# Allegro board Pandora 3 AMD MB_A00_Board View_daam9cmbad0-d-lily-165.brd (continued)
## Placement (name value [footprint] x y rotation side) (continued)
PC9094  *330P/50V_4_NC  [C0402]  116.36 149.12 90 top
PC9095  1000P/50V_4  [C0402]  116.03 150.51 0 bottom
PC9096  10U/25V_8  [C0805]  97.9 142.99 90 bottom
PC9097  10U/25V_8  [C0805]  102.05 146.49 180 bottom
PC9098  0.22U/25V_6  [C0603]  110.43 150.01 90 bottom
PC9099  680P/50V_4  [C0402]  113.92 150.51 180 bottom
PC9100  0.1U/16V_4  [C0402]  116.33 149.12 90 bottom
PC9101  22n/25V_4  [C0402]  117.29 149.12 270 bottom
PC9102  390P/50V_4  [C0402]  113.31 149.12 270 top
PC9103  2200P/50V_4  [C0402]  97.71 136.26 270 bottom
PC9104  150P/50V_4  [C0402]  114.33 149.12 270 top
PC9105  1U/6.3V_4  [C0402]  107.74 143.3 0 bottom
PC9106  1U/6.3V_4  [C0402]  107.74 144.26 0 bottom
PC9107  0.1U/16V_4  [C0402]  107.15 129.7 180 bottom
PC9108  22U/6.3V_6  [C0603]  99.78 129.9 0 top
PC9109  22U/6.3V_6  [C0603]  99.78 131.31 0 top
PC9110  330U/2V/E6_7343  [CC7343]  106.49 126.85 0 bottom
PC9111  0.1U/16V_4  [C0402]  119.32 149.12 90 bottom
PC9112  10U/25V_8  [C0805]  76.65 144.92 0 bottom
PC9113  10U/25V_8  [C0805]  76.65 144.92 0 top
PC9114  0.22U/25V_6  [C0603]  107.13 146.38 180 bottom
PC9115  2200P/50V_4  [C0402]  78.8 135.37 90 top
PC9116  0.1U/16V_4  [C0402]  89.34 132.49 180 bottom
PC9117  22U/6.3V_6  [C0603]  73.68 127.02 90 bottom
PC9119  22U/6.3V_6  [C0603]  72.26 127.02 90 bottom
PC9120  330U/2V/E6_7343  [CC7343]  75.96 132.91 90 top
PC9121  330U/2V/E6_7343  [CC7343]  73.98 103.81 270 top
PC9122  1000P/50V_4  [C0402]  115.64 145.2 180 top
PC9123  1000P/50V_4  [C0402]  115.65 142.2 180 top
PC9124  0.22U/25V_6  [C0603]  118.58 141.24 0 bottom
PC9125  120P/50V_4  [C0402]  110.82 138.07 90 bottom
PC9126  0.22U/25V_6  [C0603]  118.58 139.83 180 bottom
PC9127  390P/50V_4  [C0402]  109.8 138.07 90 bottom
PC9128  10U/25V_8  [C0805]  90.11 140.7 180 bottom
PC9129  10U/25V_8  [C0805]  88.5 142.67 90 top
PC9130  15U/25V/E100_3528  [C3528]  80.28 140.83 90 bottom
PC9131  680P/50V_4  [C0402]  111.61 136.25 270 bottom
PC9132  0.22U/25V_6  [C0603]  106.73 141.9 180 bottom
PC9133  1000P/50V_4  [C0402]  112.85 138.07 90 bottom
PC9134  0.15U/10V_4  [C0402]  115.9 138.07 90 bottom
PC9135  33n/16V_4  [C0402]  116.91 138.07 270 bottom
PC9136  *330P/50V_4_NC  [C0402]  114.76 135.5 0 bottom
PC9137  2200P/50V_4  [C0402]  87.95 137.77 270 bottom
PC9138  22U/6.3V_6  [C0603]  75.09 127.02 90 bottom
PC9140  330U/2V/E6_7343  [CC7343]  85.79 132.95 90 top
PC9141  0.1U/16V_4  [C0402]  120.39 140.47 270 bottom
PC9142  0.1U/16V_4  [C0402]  86.9 127.44 180 top
PC9143  22U/6.3V_6  [C0603]  70.85 127.02 90 bottom
PC9144  0.01U/50V_4  [C0402]  113.02 135.5 180 bottom
PC9145  1U/6.3V_4  [C0402]  39.43 126.7 270 bottom
PC9146  1U/6.3V_4  [C0402]  40.83 126.85 0 bottom
PC9147  10U/25V_8  [C0805]  72.09 142.69 90 bottom
PC9148  10U/25V_8  [C0805]  72.09 142.69 90 top
PC9149  0.22U/25V_6  [C0603]  42.84 127.28 90 bottom
PC9150  2200P/50V_4  [C0402]  71.41 137.13 180 top
PC9151  0.1U/16V_4  [C0402]  56.67 99.88 90 top
PC9152  22U/6.3V_6  [C0603]  60.74 116.73 0 top
PC9153  22U/6.3V_6  [C0603]  67.47 116.73 0 top
PC9154  22U/6.3V_6  [C0603]  57.95 115.31 180 top
PC9155  330U/2V/E6_7343  [CC7343]  59.97 132.93 90 top
PC9156  1000P/50V_4  [C0402]  35.46 116.99 270 top
PC9157  0.22U/25V_6  [C0603]  33.85 114.89 180 bottom
PC9158  10U/25V_8  [C0805]  54.37 140.7 0 bottom
PC9159  10U/25V_8  [C0805]  54.37 140.7 0 top
PC9160  15U/25V/E100_3528  [C3528]  63.83 140.45 90 bottom
PC9161  0.22U/25V_6  [C0603]  38.21 127.21 90 bottom
PC9162  120P/50V_4  [C0402]  33 127.16 90 bottom
PC9163  0.22U/25V_6  [C0603]  33.85 113.39 0 bottom
PC9164  390P/50V_4  [C0402]  32.92 128.5 0 bottom
PC9165  2200P/50V_4  [C0402]  56.96 136.5 90 top
PC9166  680P/50V_4  [C0402]  30.88 122.84 180 bottom
PC9167  22U/6.3V_6  [C0603]  57.95 116.73 180 top
PC9168  22U/6.3V_6  [C0603]  64.24 116.73 180 top
PC9169  330U/2V/E6_7343  [CC7343]  66.23 103.81 270 top
PC9170  1000P/50V_4  [C0402]  34.39 123.85 0 bottom
PC9171  0.1U/16V_4  [C0402]  58.79 100.31 90 top
PC9172  22U/6.3V_6  [C0603]  57.95 118.14 180 top
PC9173  330U/2V/E6_7343  [CC7343]  67.85 132.93 90 top
PC9174  0.15U/10V_4  [C0402]  34.52 119.3 0 bottom
PC9175  33n/16V_4  [C0402]  34.06 117.67 90 bottom
PC9176  *330P/50V_4_NC  [C0402]  30.8 117.33 180 bottom
PC9177  0.1U/16V_4  [C0402]  31.94 114.66 90 bottom
PC9178  0.01U/50V_4  [C0402]  34.09 121.51 270 bottom
PC9186  0.01U/50V_4  [C0402]  34.71 110.83 270 bottom
PC9190  10U/25V_8  [C0805]  142.81 31.72 0 top
PC9191  10U/25V_8  [C0805]  142.81 31.72 0 bottom
PC9192  0.1U/25V_4  [C0402]  142.89 30.25 0 bottom
PC9193  0.1U/25V_6  [C0603]  140.78 39.48 90 bottom
PC9194  2200P/50V_4  [C0402]  136.34 36.3 0 top
PC9195  22U/6.3V_8  [C0805]  125.41 39.48 270 bottom
PC9196  22U/6.3V_8  [C0805]  129.73 39.48 270 bottom
PC9197  22U/6.3V_8  [C0805]  129.73 39.48 270 top
PC9198  22U/6.3V_8  [C0805]  127.57 39.48 270 bottom
PC9199  22U/6.3V_8  [C0805]  127.57 39.48 270 top
PC9200  0.1U/16V_4  [C0402]  125.92 39.35 270 top
PC9201  0.01U/50V_4  [C0402]  147.62 37.66 180 bottom
PC9202  4.7U/10V_6  [C0603]  143.83 39.48 270 bottom
PC9203  10U/6.3V_4  [C0402]  123.3 50.09 90 bottom
PC9204  0.1U/25V_4  [C0402]  123.28 52.76 90 bottom
PC9205  10U/6.3V_4  [C0402]  118.38 51.69 0 bottom
PC9206  10U/6.3V_4  [C0402]  118.38 52.76 0 bottom
PC9207  0.1U/25V_4  [C0402]  124.65 54.44 180 bottom
PC9208  0.01U/50V_4  [C0402]  126.2 48.14 90 bottom
PC9209  0.033U/50V_6  [C0603]  122.03 48.09 90 bottom
PC9210  10U/6.3V_6  [C0603]  118.34 29.57 90 bottom
PC9211  0.1U/16V_4  [C0402]  117.16 29.78 90 bottom
PC9212  0.01U/50V_4  [C0402]  120.08 30.08 90 bottom
PC9213  1U/6.3V_4  [C0402]  117.41 32.35 270 bottom
PC9214  10U/6.3V_6  [C0603]  117.79 42.62 270 bottom
PC9216  10U/25V_8  [C0805]  16.29 36.73 0 bottom
PC9217  10U/25V_8  [C0805]  19.36 34.3 90 top
PC9219  *2200P/50V_4_NC  [C0402]  22.21 35.44 0 top
PC9221  0.1U/16V_4  [C0402]  17.46 27.21 90 bottom
PC9222  10U/4V_8  [C0805]  15.66 43.64 0 bottom
PC9225  22U/6.3V_8  [C0805]  27.17 27.13 90 bottom
PC9226  22U/6.3V_8  [C0805]  25.13 27.13 90 bottom
PC9227  22U/6.3V_8  [C0805]  25.13 27.13 90 top
PC9228  22U/6.3V_8  [C0805]  27.17 27.13 90 top
PC9229  22U/6.3V_8  [C0805]  15.91 27.54 90 bottom
PC9230  10U/4V_8  [C0805]  15.66 41.61 0 bottom
PC9233  10U/6.3V_6  [C0603]  15.98 53.6 0 bottom
PC9234  0.1U/16V_4  [C0402]  16.41 54.84 0 bottom
PC9235  1U/6.3V_4  [C0402]  16.41 52.35 0 bottom
PC9236  1U/6.3V_4  [C0402]  19.91 56.43 180 bottom
PC9237  10U/6.3V_6  [C0603]  26.7 55.09 270 bottom
PC9238  10U/25V_8  [C0805]  158.06 61.96 0 bottom
PC9239  10U/25V_8  [C0805]  158.06 61.96 0 top
PC9240  *330P/50V_4_NC  [C0402]  146.54 47.7 0 top
PC9241  0.22U/25V_6  [C0603]  147.41 55.1 90 bottom
PC9242  1000P/50V_4  [C0402]  147.14 48.06 270 bottom
PC9243  2200P/50V_4  [C0402]  154.12 65.26 90 top
PC9244  680P/50V_4  [C0402]  149.22 49.92 90 bottom
PC9245  0.01U/50V_4  [C0402]  148.33 44.75 180 bottom
PC9246  47n/16V_4  [C0402]  146.49 44.75 0 bottom
PC9247  0.1U/16V_4  [C0402]  156.02 76.43 270 top
PC9248  22U/6.3V_6  [C0603]  147.54 80.63 270 bottom
PC9249  22U/6.3V_6  [C0603]  150.46 80.63 270 top
PC9250  330U/2V/E6_7343  [CC7343]  150.69 74.4 270 top
PC9251  390P/50V_4  [C0402]  146.54 49.8 180 top
PC9252  100P/50V_4  [C0402]  146.08 49.92 90 bottom
PC9253  1U/6.3V_4  [C0402]  139.31 55.05 180 bottom
PC9254  1U/6.3V_4  [C0402]  141.06 55.05 0 bottom
PC9255  0.1U/16V_4  [C0402]  147.14 46.21 270 bottom
PC9256  10U/25V_8  [C0805]  131.13 59.8 270 top
PC9258  10U/25V_8  [C0805]  133.29 59.8 270 top
PC9259  0.22U/25V_6  [C0603]  143.15 55.1 90 bottom
PC9260  2200P/50V_4  [C0402]  141.67 66.78 0 top
PC9261  0.1U/16V_4  [C0402]  137.2 96.92 90 top
PC9262  330U/2V/E6_7343  [CC7343]  137.22 74.4 270 top
PC9263  330U/2V/E6_7343  [CC7343]  129.6 74.4 270 top
PC9264  *0.1U/16V_4_NC  [C0402]  138.34 42.88 270 bottom
PC9265  1000P/50V_4  [C0402]  141.17 47.44 90 top
PC9266  1000P/50V_4  [C0402]  140.15 47.44 90 top
PC9267  15U/25V/E100_3528  [C3528]  138.49 61.57 270 bottom
PC9268  0.22U/25V_6  [C0603]  135.98 44.53 270 bottom
PC9269  10U/25V_8  [C0805]  147.77 59.8 270 top
PC9270  10U/25V_8  [C0805]  145.73 59.8 270 top
PC9271  100P/50V_4  [C0402]  135.39 50.76 0 top
PC9272  0.22U/25V_6  [C0603]  137.75 55.22 90 bottom
PC9273  0.22U/25V_6  [C0603]  134.56 44.53 90 bottom
PC9274  390P/50V_4  [C0402]  135.4 51.77 0 bottom
PC9275  680P/50V_4  [C0402]  135.39 52.79 180 top
PC9276  2200P/50V_4  [C0402]  129.73 66.53 180 top
PC9277  330U/2V/E6_7343  [CC7343]  145.86 74.4 270 top
PC9278  1000P/50V_4  [C0402]  133.36 49.74 0 bottom
PC9279  0.1U/16V_4  [C0402]  125.87 77.42 90 top
PC9280  330U/2V/E6_7343  [CC7343]  139.26 106.53 0 top
PC9281  0.22U/16V_4  [C0402]  135.6 46.41 0 bottom
PC9282  68n/16V_4  [C0402]  135.6 47.38 0 bottom
PC9283  *330P/50V_4_NC  [C0402]  135.4 48.72 0 bottom
PC9284  0.1U/16V_4  [C0402]  135.8 42.6 180 bottom
PC9285  0.01U/50V_4  [C0402]  136 49.33 270 top
PC9286  10U/25V_8  [C0805]  165.67 63.86 270 bottom
PC9287  10U/25V_8  [C0805]  165.8 63.86 270 top
PC9288  0.1U/25V_4  [C0402]  167.16 59.42 90 bottom
PC9289  0.1U/25V_6  [C0603]  174.33 66.3 0 bottom
PC9290  2200P/50V_4  [C0402]  165.43 67.92 0 bottom
PC9291  22U/6.3V_8  [C0805]  165.9 78.97 0 bottom
PC9292  22U/6.3V_8  [C0805]  165.9 76.97 0 bottom
PC9293  22U/6.3V_8  [C0805]  173.67 77.2 180 bottom
PC9294  22U/6.3V_8  [C0805]  173.8 79.35 180 bottom
PC9295  0.1U/16V_4  [C0402]  174.69 73.64 180 bottom
PC9296  *0.1U/25V_4_NC  [C0402]  171.08 59.42 90 bottom
PC9297  0.01U/50V_4  [C0402]  173.06 59.42 90 bottom
PC9298  4.7U/10V_6  [C0603]  174.33 63.43 180 bottom
PC9299  *0.1u/16V_4_NC  [C0402]  123.09 63.09 180 bottom
PC9300  *0.1u/16V_4_NC  [C0402]  116.19 69.19 180 bottom
PC9301  *0.1u/16V_4_NC  [C0402]  113.45 63.09 180 bottom
PC9302  22u/6.3V_6  [C0603]  113.5 69.5 0 bottom
PC9303  22u/6.3V_6  [C0603]  121.77 69.11 180 bottom
PC9304  0.1u/16V_4  [C0402]  121.49 67.82 180 bottom
PC9305  0.1U/10V_4  [C0402]  124.88 27.11 180 bottom
PC9306  0.1U/10V_4  [C0402]  165.42 26.14 0 bottom
PC9307  0.1U/10V_4  [C0402]  165.37 21.29 0 bottom
PC9308  0.1U/10V_4  [C0402]  124.88 22.41 180 bottom
PC9309  10U/6.3V_4  [C0402]  118.28 27.49 0 bottom
PC9310  0.1U/10V_4  [C0402]  118.28 26.34 0 bottom
PC9311  0.1U/10V_4  [C0402]  118.28 23.17 0 bottom
PC9312  10U/6.3V_4  [C0402]  120.82 22.33 180 bottom
PC9313  10U/6.3V_4  [C0402]  161.71 26.5 0 bottom
PC9314  0.1U/10V_4  [C0402]  161.71 25.48 0 bottom
PC9315  0.1U/10V_4  [C0402]  160.82 22.31 0 bottom
PC9316  10U/6.3V_4  [C0402]  160.85 21.29 0 bottom
PC9317  0.1U/10V_4  [C0402]  124.88 24.82 0 bottom
PC9318  0.1U/10V_4  [C0402]  168.31 24.34 0 bottom
PC9319  0.01U/50V_4  [C0402]  124.88 25.96 180 bottom
PC9320  0.1U/10V_4  [C0402]  124.88 23.68 180 bottom
PC9321  0.01U/50V_4  [C0402]  168.31 25.38 180 bottom
PC9322  0.1U/10V_4  [C0402]  168.31 22.98 180 bottom
PC9323  1000P/50V_4  [C0402]  118.28 25.2 0 bottom
PC9324  1000P/50V_4  [C0402]  118.28 24.19 0 bottom
PC9325  1000P/50V_4  [C0402]  161.71 24.34 0 bottom
PC9326  1000P/50V_4  [C0402]  161.71 23.32 0 bottom
PC9327  0.1U/10V_4  [C0402]  151.32 28.94 270 bottom
PC9328  0.1U/10V_4  [C0402]  156.02 28.94 270 bottom
PC9329  10U/6.3V_4  [C0402]  149.7 22.94 0 bottom
PC9330  0.1U/16V_4  [C0402]  151.73 23.2 270 bottom
PC9331  0.1U/16V_4  [C0402]  155.54 23.2 270 bottom
PC9332  10U/6.3V_4  [C0402]  157.57 22.94 180 bottom
PC9333  0.1U/16V_4  [C0402]  153.89 28.91 90 bottom
PC9334  0.1U/10V_4  [C0402]  152.34 28.94 270 bottom
PC9335  0.1U/10V_4  [C0402]  154.9 28.91 270 bottom
PC9336  1000P/50V_4  [C0402]  153 23.2 90 bottom
PC9337  1000P/50V_4  [C0402]  154.27 23.2 90 bottom
PC9338  0.1U/25V_6  [C0603]  15.96 38.44 180 bottom
PC9340  0.1U/16V_4  [C0402]  30.54 89.13 0 bottom
PC9341  22U/6.3V_8  [C0805]  36.01 91.04 180 bottom
PC9342  22U/6.3V_8  [C0805]  36.01 93.2 180 bottom
PC9343  2200P/50V_4  [C0402]  34.56 99.67 180 top
PC9344  0.1U/25V_6  [C0603]  31.43 104.32 180 bottom
PC9345  10U/25V_8  [C0805]  39.48 105.64 90 top
PC9346  4.7U/10V_6  [C0603]  31.18 107.52 0 bottom
PC9347  22U/6.3V_8  [C0805]  31.31 91.04 0 bottom
PC9348  10U/25V_8  [C0805]  39.48 105.64 90 bottom
PC9349  0.1U/25V_4  [C0402]  40.4 107.88 180 top
PC9350  0.01U/50V_4  [C0402]  32.13 110.83 270 bottom
PC9351  22U/6.3V_8  [C0805]  31.31 93.2 0 bottom
PC9353  *10U/6.3V_4_NC  [C0402]  38.42 85.55 270 bottom
PC9354  4700P/25V_4  [C0402]  135.7 28.4 180 bottom
PC9355  0.1U/16V_4  [C0402]  127.84 28.07 90 bottom
PC9356  22U/6.3V_8  [C0805]  37.15 88.24 90 bottom
PC9357  15U/25V/E100_3528  [C3528]  80.2 140.85 90 top
PC9358  15U/25V/E100_3528  [C3528]  63.82 140.44 90 top
PC9359  10U/25V_8  [C0805]  128.59 59.8 270 top
PC9360  10U/25V_8  [C0805]  149.74 59.8 270 top
PC9361  0.1U/25V_4  [C0402]  24.3 47.16 180 bottom
PC9362  0.1U/10V_4  [C0402]  30.43 79.08 270 bottom
PC9363  0.1U/10V_4  [C0402]  135.7 29.49 180 bottom
PC9364  *1U/6.3V_4_NC  [C0402]  118.17 141.2 180 top
PC9365  *0.1U/10V_4_NC  [C0402]  118.17 139.81 0 top
PC9366  *1U/6.3V_4_NC  [C0402]  41.39 116.95 90 top
PC9367  *0.1U/10V_4_NC  [C0402]  37.43 117 270 top
PC9368  0.01U/50V_4  [C0402]  145.86 37.42 270 top
PC9369  0.1U/16V_4  [C0402]  138.54 44.81 270 bottom
PC9370  22U/6.3V_8  [C0805]  175.07 75.16 180 bottom
PC9371  1000P/50V_4  [C0402]  113.98 145.85 270 top
PC9372  1000P/50V_4  [C0402]  114.28 141.05 90 top
PC9373  1000P/50V_4  [C0402]  34.17 116.87 270 top
PC9374  1000P/50V_4  [C0402]  143.27 47.8 90 top
PC9375  1000P/50V_4  [C0402]  137.34 47.96 90 top
PC9376  *2.2U/25V_4_NC  [C0402]  62.68 9.38 180 top
PD1  BAV99W-7-F  [UMT_213-3-1_3]  59.55 15.63 90 bottom
PD2  *BAS316_NC  [DSM]  52.59 12.78 0 bottom
PD3  1SS355VM  [DSM]  79.13 7.88 0 bottom
PD4  1SS355VM  [DSM]  79.11 5.95 0 bottom
PD5  BAT54SW-7-F  [UMT_213-3-1_3]  146.04 17.3 270 bottom
PD6  BAT54SW-7-F  [UMT_213-3-1_3]  144.39 9.2 270 bottom
PD7  1SS355  [DSMV]  51.45 16.11 0 top
PL15  6.8UH20%8A(PCMC063T-6R8MN)  [CHOKE-PCMC063T-3R3MN-SMT]  93.38 12.25 0 bottom
PL16  2.2UH20%14A(PCMC063T-2R2MN)  [CHOKE-PCMC063T-3R3MN-SMT]  171.49 10.7 270 bottom
PL17  2.2UH20%14A(PCMC063T-2R2MN)  [CHOKE-PCMC063T-3R3MN-SMT]  130.62 8.62 90 bottom
PL18  0.36U PCME064T-R36MS1R407  [CHOKE-PCMC063T-R82MN-4P-SMT]  101.76 133.72 270 bottom
PL19  0.24UH (PCME064T-R24MS1R007)  [CHOKE-PCMC063T-R82MN-4P-SMT]  75.88 132.84 270 bottom
PL20  0.24UH (PCME064T-R24MS1R007)  [CHOKE-PCMC063T-R82MN-4P-SMT]  84.74 132.84 270 bottom
PL21  0.24UH ( PCME064T-R24MS1R007)  [CHOKE-PCMC063T-R82MN-4P-SMT]  68.06 132.84 270 bottom
PL22  0.24UH ( PCME064T-R24MS1R007)  [CHOKE-PCMC063T-R82MN-4P-SMT]  60.07 132.84 270 bottom
PL24  2.2UH20%14A(PCMC063T-2R2MN)  [CHOKE-PCMC063T-3R3MN-SMT]  135.45 36.05 0 bottom
PL25  1UH 20%11A(PCMC063T-1R0MN)  [CHOKE-PCMC063T-3R3MN-SMT]  20.38 32.11 90 bottom
PL26  1UH 20%11A(PCMC063T-1R0MN)  [CHOKE-PCMC063T-3R3MN-SMT]  151.45 71.1 270 bottom
PL27  0.22U20%50A(PCME104T-R22MS0R607)  [CHOKE-PCMB104T-R45MN-4P-SMT]  142.69 72.75 90 bottom
PL28  0.22U20%50A(PCME104T-R22MS0R607)  [CHOKE-PCMB104T-R45MN-4P-SMT]  132.02 72.75 90 bottom
PL29  1UH 20%11A(PCMC063T-1R0MN)  [CHOKE-PCMC063T-3R3MN-SMT]  169.61 72.24 270 bottom
PL31  1UH 20%11A(PCMC063T-1R0MN)  [CHOKE-PCMC063T-3R3MN-SMT]  34.23 99.04 90 bottom
PQ28  MMST3904-7-F  [UMT_213-3-1_3]  55.49 15.73 90 bottom
PQ29  FDV301N  [SOT23_213-3_3-2]  52.16 15.6 0 bottom
PQ30  *LU1L002SNFS8_NC  [SOT323_213-2_1-1_3-2N7002W]  62.42 14.05 0 bottom
PQ31  2N7002W  [UMT_213-3-1_3]  38.42 14.03 270 bottom
PQ32  AON7408  [PG-TSDSON-8-8P-R]  86.45 14.03 180 bottom
PQ33  AON7400AL  [PG-TSDSON-8-8P-R]  100.29 13.54 180 bottom
PQ35  AON7752  [PG-TSDSON-8-8P-R]  165.19 11.77 180 bottom
PQ36  2N7002W  [UMT_213-3-1_3]  39.21 10.67 180 bottom
PQ37  AON7408  [PG-TSDSON-8-8P-R]  86.45 10.27 0 bottom
PQ38  AON7400AL  [PG-TSDSON-8-8P-R]  136.51 9.63 180 bottom
PQ39  AON7408  [PG-TSDSON-8-8P-R]  165.19 8.03 0 bottom
PQ40  AON7400AL  [PG-TSDSON-8-8P-R]  55.08 6.91 90 bottom
PQ41  AON7400AL  [PG-TSDSON-8-8P-R]  58.79 6.91 90 bottom
PQ42  AON7516  [PG-TSDSON-8-8P-R]  136.51 5.9 0 bottom
PQ43  2N7002KDW  [SOT-363]  55.82 12.71 180 top
PQ44  MMBT3906W  [UMT_213-3-1_3]  52.46 13.52 90 top
PQ45  AOE6930  [POWER-5X6-1_27-10P]  101.66 141.59 0 bottom
PQ46  AOE6930  [POWER-5X6-1_27-10P]  75.88 140.63 0 bottom
PQ47  AOE6930  [POWER-5X6-1_27-10P]  84.74 140.63 0 bottom
PQ48  AOE6930  [POWER-5X6-1_27-10P]  68.4 140.63 0 bottom
PQ49  AOE6930  [POWER-5X6-1_27-10P]  59.25 140.69 0 bottom
PQ52  AON7516  [PG-TSDSON-8-8P-R]  34.61 80.89 0 bottom
PQ53  AO6402A  [TSOP6-2_8-95]  128.21 30.84 0 bottom
PQ54  AO6402A  [TSOP6-2_8-95]  121.07 51.57 270 bottom
PQ57  AON7400AL  [PG-TSDSON-8-8P-R]  158.31 65 180 bottom
PQ58  AON7516  [PG-TSDSON-8-8P-R]  153.86 63.86 270 bottom
PQ59  AOE6930  [POWER-5X6-1_27-10P]  143.32 61.83 180 bottom
PQ60  AOE6930  [POWER-5X6-1_27-10P]  149.04 61.83 180 bottom
PQ61  AOE6930  [POWER-5X6-1_27-10P]  133.67 61.83 180 bottom
PQ62  AOE6930  [POWER-5X6-1_27-10P]  127.95 61.83 180 bottom
PQ63  AO3416  [SOT23_213-3_3-2]  122.21 60.76 270 bottom
PQ64  AO3416  [SOT23_213-3_3-2]  122.21 65.42 270 bottom
PQ65  2N7002K  [SOT23_213-3_3-2]  117.36 55.17 180 bottom
PQ66  2N7002K  [SOT23_213-3_3-2]  117.44 49 270 bottom
PQ67  AO3416  [SOT23_213-3_3-2]  113.2 60.76 270 bottom
PQ68  AO3416  [SOT23_213-3_3-2]  113.2 65.42 270 bottom
PQ70  2N7002KDW  [SOT-363]  32.83 77.2 90 bottom
PQ71  2N7002KDW  [SOT-363]  132.78 29.32 0 bottom
PQ72  AO6402A  [TSOP6-2_8-95]  265.01 60.53 270 top
PQ73  AON7516  [PG-TSDSON-8-8P-R]  34.61 84.6 0 bottom
PR60  *2.2_8_NC  [R0805]  137.3 6.13 180 top
PR61  2.2_12  [R1206]  57.75 6.71 180 top
PR62  *100K_4_NC  [R0402]  143.73 6.63 270 bottom
PR103  5.49K/F_4  [R0402]  25.64 43.03 270 bottom
PR107  2.2_6  [R0603]  25.41 45.37 270 bottom
PR111  *10K_4_NC  [R0402]  22.95 47.48 270 bottom
PR113  10K/F_4  [R0402]  18.61 46.97 270 bottom
PR115  499K/F_4  [R0402]  23.05 44.94 90 bottom
PR120  10K_4  [R0402]  21.91 44.94 90 bottom
PR121  6.04K/F_4  [R0402]  19.62 46.97 90 bottom
PR175  100K_4  [R0402]  30.04 75.67 180 bottom
PR178  100K_4  [R0402]  34.99 77.07 0 bottom
PR185  6.8K_4  [R0402]  38.51 17.47 0 bottom
PR186  15K/F_4  [R0402]  49.82 15.78 270 bottom
PR187  4.02K/F_6  [R0603]  69.36 16.13 270 bottom
PR188  10_6  [R0603]  70.85 16.13 90 bottom
PR189  10_6  [R0603]  72.35 16.13 90 bottom
PR190  10_6  [R0603]  67.86 16.13 270 bottom
PR191  3K/F_4  [R0402]  66.23 16.46 90 bottom
PR192  100K/F_4  [R0402]  76.21 13.98 90 bottom
PR193  100K/F_4  [R0402]  50.44 14.34 0 bottom
PR194  6.8K_4  [R0402]  38.51 16.45 0 bottom
PR195  *1M/F_4_NC  [R0402]  62.83 15.75 0 bottom
PR196  10K/F_4  [R0402]  57.59 14.75 270 bottom
PR199  44.2K/F_4  [R0402]  74 13.98 270 bottom
PR200  *SJ0402_NC  [S0402]  66.03 14.36 180 bottom
PR201  *1M/F_4_NC  [R0402]  64.29 13.75 90 bottom
PR202  33_4  [R0402]  58.99 13.31 0 bottom
PR203  2.2K_4  [R0402]  57.21 13.31 180 bottom
PR204  86.6K/F_4  [R0402]  153.25 13.9 270 bottom
PR205  *SJ0402_NC  [S0402]  145.66 13.85 90 bottom
PR206  20K/F_4  [R0402]  151.09 13.87 270 bottom
PR207  13K/F_4  [R0402]  152.18 13.87 270 bottom
PR208  60.4K/F_4  [R0402]  146.75 13.85 90 bottom
PR209  30.9K/F_4  [R0402]  147.84 13.85 90 bottom
PR210  20K/F_4  [R0402]  148.88 13.85 90 bottom
PR211  *SJ0402_NC  [S0402]  66.03 13.37 180 bottom
PR214  100K/F_4  [R0402]  40.42 13.67 90 bottom
PR215  *SJ0402_NC  [S0402]  66.03 12.37 180 bottom
PR217  4.02K/F_6  [R0603]  61.56 11.54 90 bottom
PR218  4.02K/F_6  [R0603]  63.08 11.54 90 bottom
PR220  0.01_0612  [RC3216-4P]  105.98 10.95 270 bottom
PR221  100_4  [R0402]  116.09 10.5 270 bottom
PR222  10K/F_4  [R0402]  117.18 10.5 270 bottom
PR223  100_4  [R0402]  113.14 10.47 270 bottom
PR224  100_4  [R0402]  114.64 10.47 270 bottom
PR225  *2.2_8_NC  [R0805]  177.99 10.14 180 bottom
PR226  1_6  [R0603]  153.86 9.71 180 bottom
PR227  1_6  [R0603]  147.38 6.33 180 bottom
PR228  221K/F_4  [R0402]  66.56 7.96 270 bottom
PR229  35.7K/F_4  [R0402]  67.58 7.96 90 bottom
PR230  *SJ0402_NC  [S0402]  69.61 7.96 270 bottom
PR232  0.01_0612  [RC3216-4P]  62.24 7.09 270 bottom
PR234  10_12  [R1206]  75.52 6.87 270 bottom
PR235  2.2_8  [R0805]  89.98 5.95 90 bottom
PR236  10K/F_4  [R0402]  68.44 5.97 90 bottom
PR237  8.06K/F_4  [R0402]  67.42 5.97 270 bottom
PR242  100K_4  [R0402]  58.18 12.53 90 top
PR243  100K_4  [R0402]  49.85 14.33 270 top
PR244  680K_4  [R0402]  52.52 11.1 180 top
PR245  10K_4  [R0402]  58.18 14.44 90 top
PR246  10_4  [R0402]  117.38 149.12 90 top
PR247  *SJ0402_NC  [S0402]  118.39 149.12 90 top
PR249  1.82K/F_4  [R0402]  116.02 150.53 0 top
PR250  300_4  [R0402]  115.37 149.12 90 bottom
PR251  2.61K/F_4  [R0402]  106.08 134.24 270 bottom
PR252  1_6  [R0603]  109.02 150.01 270 bottom
PR253  2K/F_4  [R0402]  114.41 149.12 90 bottom
PR254  1_6  [R0603]  105.96 144.01 270 bottom
PR255  11K/F_4  [R0402]  118.31 149.12 90 bottom
PR256  33K/F_4  [R0402]  113.45 149.12 90 bottom
PR257  133K/F_4  [R0402]  113.94 150.66 180 top
PR258  10K/F_4_3435NTC  [R0402]  106.08 132.33 90 bottom
PR259  523/F_4  [R0402]  119.41 149.12 270 top
PR260  2.2_8  [R0805]  97.42 138.9 270 bottom
PR261  3.65K/F_6  [R0603]  121.72 148.19 180 bottom
PR263  1/F_4  [R0402]  121.02 149.5 0 bottom
PR264  *SJ0402_NC  [S0402]  115.35 149.12 90 top
PR265  *SJ0402_NC  [S0402]  118.94 146.36 0 bottom
PR266  *SJ0402_NC  [S0402]  118.43 144.38 0 top
PR267  *SJ0402_NC  [S0402]  118.94 145.37 0 bottom
PR268  *SJ0402_NC  [S0402]  118.43 143.36 0 top
PR269  *SJ0402_NC  [S0402]  118.94 144.38 0 bottom
PR270  20K_4  [R0402]  119.95 141.2 0 top
PR271  1_6  [R0603]  107.13 147.8 0 bottom
PR273  *SJ0402_NC  [S0402]  119.95 140.06 0 top
PR274  2.2_8  [R0805]  80.4 136.1 270 top
PR275  220K/B4500/5%_4  [R0402]  106.49 135.62 180 bottom
PR276  27.4K/F_4  [R0402]  118.43 145.39 0 top
PR277  220K/B4500/5%_4  [R0402]  89.35 134.6 180 bottom
PR278  27.4K/F_4  [R0402]  117.92 142.85 90 bottom
PR279  3.65K/F_6  [R0603]  118.14 136.72 90 bottom
PR280  13.7K/F_4  [R0402]  118.43 146.41 180 top
PR281  13.7K/F_4  [R0402]  120.46 142.85 90 bottom
PR282  133K/F_4  [R0402]  115.62 144.21 180 top
PR283  133K/F_4  [R0402]  115.63 143.22 180 top
PR284  10K/F_4  [R0402]  118.14 136.72 270 top
PR285  1/F_4  [R0402]  81.17 133.48 180 top
PR287  210K/F_4  [R0402]  108.78 138.07 270 bottom
PR288  133K/F_4  [R0402]  110.2 136.64 180 bottom
PR289  2K/F_4  [R0402]  111.83 138.07 270 bottom
PR290  1_6  [R0603]  106.73 140.49 0 bottom
PR291  2.61K/F_4  [R0402]  91.53 134.63 180 bottom
PR292  300_4  [R0402]  113.08 136.64 180 bottom
PR293  11K/F_4  [R0402]  118.33 138.64 180 bottom
PR294  10_4  [R0402]  114.76 134.48 0 bottom
PR295  2.49K/F_4  [R0402]  113.86 138.07 90 bottom
PR296  10K/F_4_3435NTC  [R0402]  89.35 133.46 0 bottom
PR297  *SJ0402_NC  [S0402]  114.75 133.43 0 bottom
PR298  619/F_4  [R0402]  114.88 138.07 90 bottom
PR299  2.2_8  [R0805]  90.11 138.66 180 bottom
PR300  *SJ0402_NC  [S0402]  112.99 133.43 180 bottom
PR301  10_4  [R0402]  113.02 134.48 0 bottom
PR302  3.65K/F_6  [R0603]  119.56 136.72 90 bottom
PR303  10K/F_4  [R0402]  119.56 136.72 270 top
PR304  1/F_4  [R0402]  81.17 132.09 0 top
PR305  1_6  [R0603]  40.45 128.27 180 bottom
PR307  10K/F_4  [R0402]  44.33 121.76 0 bottom
PR308  1_6  [R0603]  44.26 127.28 270 bottom
PR309  *SJ0402_NC  [S0402]  41.36 116.94 270 bottom
PR310  10K/F_4  [R0402]  44.33 122.82 0 bottom
PR311  *SJ0402_NC  [S0402]  41.4 113.77 0 bottom
PR312  *SJ0402_NC  [S0402]  44.35 123.8 180 bottom
PR313  2.2_8  [R0805]  71.18 135.03 90 top
PR314  *SJ0402_NC  [S0402]  40.15 116.99 270 bottom
PR316  *SJ0402_NC  [S0402]  37.45 116.99 270 bottom
PR317  3.65K/F_6  [R0603]  36.64 114.91 180 bottom
PR318  47K_4  [R0402]  40.37 116.95 270 top
PR319  10K/F_4  [R0402]  36.64 114.91 0 top
PR321  *SJ0402_NC  [S0402]  39.2 116.98 270 top
PR322  1/F_4  [R0402]  64.7 132.2 90 top
PR323  220K/B4500/5%_4  [R0402]  55.82 132.81 270 bottom
PR324  27.4K/F_4  [R0402]  35.47 117 270 bottom
PR325  100K_4  [R0402]  42.74 117.2 180 top
PR326  13.7K/F_4  [R0402]  36.49 117 270 bottom
PR327  100K_4  [R0402]  42.99 117.33 180 bottom
PR328  133K/F_4  [R0402]  36.47 117 270 top
PR330  1_6  [R0603]  36.39 127.21 270 bottom
PR331  210K/F_4  [R0402]  33.96 127.16 270 bottom
PR332  133K/F_4  [R0402]  32.53 125.31 90 bottom
PR333  2K/F_4  [R0402]  32.67 123.85 180 bottom
PR334  2.2_8  [R0805]  54.67 136.38 0 top
PR335  2.61K/F_4  [R0402]  55.79 128.53 90 bottom
PR336  300_4  [R0402]  33.49 125.31 270 bottom
PR337  11K/F_4  [R0402]  32.7 116.18 180 bottom
PR338  10_4  [R0402]  30.8 119.11 0 bottom
PR339  2.49K/F_4  [R0402]  34.47 125.19 270 bottom
PR340  10K/F_4_3435NTC  [R0402]  55.79 130.48 270 bottom
PR341  3.65K/F_6  [R0603]  36.64 113.39 180 bottom
PR342  *SJ0402_NC  [S0402]  32.66 122.84 0 bottom
PR343  604/F_4  [R0402]  32.7 117.2 180 bottom
PR344  10K/F_4  [R0402]  36.64 113.52 0 top
PR345  1/F_4  [R0402]  63.31 131.81 180 top
PR346  *SJ0402_NC  [S0402]  32.34 121.86 0 bottom
PR347  10_4  [R0402]  32.34 120.85 0 bottom
PR353  *SJ0402_NC  [S0402]  33.4 110.83 90 bottom
PR359  1_6  [R0603]  142.3 39.48 270 bottom
PR360  150K/F_4  [R0402]  146.24 33.13 90 bottom
PR361  2.2_8  [R0805]  135.57 33.89 90 top
PR362  26.1K/F_4  [R0402]  148.4 35.03 90 bottom
PR363  10_6  [R0603]  145.35 39.48 270 bottom
PR364  20.5K/F_4  [R0402]  147.26 35.03 270 bottom
PR366  54.9/F_4  [R0402]  124.96 46 90 bottom
PR368  *0_4_NC  [R0402]  126.2 46 270 bottom
PR369  47/F_6  [R0603]  120.51 48.09 270 bottom
PR370  100/F_4  [R0402]  124.96 48.14 270 bottom
PR373  *SJ0402_NC  [S0402]  121.1 30.08 90 bottom
PR374  45.3K/F_4  [R0402]  119.7 40.37 180 bottom
PR375  51.1K/F_4  [R0402]  121.73 40.37 180 bottom
PR382  *2.2_8_NC  [R0805]  22.34 33.15 180 top
PR386  10K_4  [R0402]  16.41 50.32 180 bottom
PR387  88.7K/F_4  [R0402]  26.69 52.91 90 bottom
PR388  41.2K/F_4  [R0402]  26.69 50.42 90 bottom
PR390  10_4  [R0402]  148.21 48.06 90 bottom
PR391  *SJ0402_NC  [S0402]  149.22 48.06 270 bottom
PR392  1_6  [R0603]  145.99 55.1 270 bottom
PR393  1.69K/F_4  [R0402]  146.08 48.06 270 bottom
PR394  2K/F_4  [R0402]  147.14 49.92 270 bottom
PR395  2.61K/F_4  [R0402]  156.52 71.49 180 bottom
PR396  2K/F_4  [R0402]  148.21 49.92 270 bottom
PR397  1_6  [R0603]  140.37 56.24 180 bottom
PR398  2.2_8  [R0805]  154.62 62.97 180 top
PR399  11K/F_4  [R0402]  148.21 46.21 90 bottom
PR400  33K/F_4  [R0402]  146.54 50.82 0 top
PR401  133K/F_4  [R0402]  146.54 48.71 0 top
PR402  10K/F_4_3435NTC  [R0402]  156.52 70.53 180 bottom
PR403  1.37K/F_4  [R0402]  146.08 46.21 90 bottom
PR404  3.65K/F_6  [R0603]  150.91 45.07 180 bottom
PR405  1/F_4  [R0402]  149.94 46.59 0 bottom
PR406  *SJ0402_NC  [S0402]  144.59 44.81 90 bottom
PR407  10K/F_4  [R0402]  132.96 53.8 0 bottom
PR408  1_6  [R0603]  144.56 55.1 270 bottom
PR409  *0_4_NC  [R0402]  143.57 44.81 270 bottom
PR410  *SJ0402_NC  [S0402]  141.54 44.81 90 bottom
PR411  *SJ0402_NC  [S0402]  140.55 44.81 90 bottom
PR412  2.2_8  [R0805]  139 66.65 0 top
PR413  *SJ0402_NC  [S0402]  139.56 44.81 90 bottom
PR414  *SJ0402_NC  [S0402]  139.41 42.88 90 bottom
PR416  *SJ0402_NC  [S0402]  137.35 42.88 90 bottom
PR417  3.65K/F_6  [R0603]  132.27 45.57 0 bottom
PR418  10K/F_4  [R0402]  132.43 45.54 180 top
PR419  1/F_4  [R0402]  141.42 73.77 0 top
PR420  220K/B4500/5%_4  [R0402]  155.89 73.89 90 bottom
PR421  27.4K/F_4  [R0402]  146.44 43.67 0 bottom
PR422  220K/B4500/5%_4  [R0402]  125.03 67.67 0 bottom
PR423  27.4K/F_4  [R0402]  135.01 47.48 180 top
PR424  13.7K/F_4  [R0402]  148.37 43.67 0 bottom
PR425  13.7K/F_4  [R0402]  135.01 46.46 0 top
PR426  133K/F_4  [R0402]  142.18 47.44 90 top
PR427  133K/F_4  [R0402]  139.16 47.44 90 top
PR429  1_6  [R0603]  136.34 55.22 270 bottom
PR430  200K/F_4  [R0402]  135.4 52.79 180 bottom
PR431  133K/F_4  [R0402]  133.36 52.79 0 bottom
PR432  2K/F_4  [R0402]  135.39 51.77 0 top
PR433  300_4  [R0402]  132.7 51.28 270 bottom
PR434  2.2_8  [R0805]  132.53 66.53 180 top
PR435  2.61K/F_4  [R0402]  125.03 68.69 180 bottom
PR436  953/F_4  [R0402]  133.72 51.28 270 bottom
PR437  11K/F_4  [R0402]  134.15 47.3 270 bottom
PR438  10_4  [R0402]  135.4 49.74 180 bottom
PR439  10K/F_4_3435NTC  [R0402]  125.03 69.7 180 bottom
PR440  3.65K/F_6  [R0603]  132.27 47.1 0 bottom
PR441  10K/F_4  [R0402]  132.43 46.81 180 top
PR442  *SJ0402_NC  [S0402]  133.36 48.7 0 bottom
PR443  442/F_4  [R0402]  133.36 43.87 90 bottom
PR444  1/F_4  [R0402]  133.16 73.64 180 top
PR445  *SJ0402_NC  [S0402]  134.98 49.33 90 top
PR446  10_4  [R0402]  135.4 50.75 0 bottom
PR447  1_6  [R0603]  174.33 64.85 180 bottom
PR449  100K/F_4  [R0402]  168.12 59.42 90 bottom
PR450  *SJ0402_NC  [S0402]  172.07 59.42 270 bottom
PR451  2.2_8  [R0805]  165.04 70.21 270 bottom
PR452  14K/F_4  [R0402]  170.09 59.42 270 bottom
PR453  10_6  [R0603]  174.33 61.98 180 bottom
PR454  20K/F_4  [R0402]  169.13 59.42 90 bottom
PR455  1K/F_4  [R0402]  119.32 59.02 0 bottom
PR456  100K/F_4  [R0402]  118.28 46.18 180 bottom
PR457  100K/F_4  [R0402]  115.84 51.82 90 bottom
PR458  *0_4_NC  [R0402]  117.41 60.13 0 bottom
PR460  100K/F_4  [R0402]  116.47 57.51 0 bottom
PR461  1K/F_4  [R0402]  114.61 58.42 180 bottom
PR462  *0_4_NC  [R0402]  119.32 60.13 0 bottom
PR463  *SJ0402_NC  [S0402]  170.09 25.38 0 bottom
PR465  *SJ0402_NC  [S0402]  126.68 26.04 0 bottom
PR467  10K/F_4  [R0402]  153.66 31.07 270 bottom
PR468  10K/F_4  [R0402]  154.78 31.07 90 bottom
PR469  1_6  [R0603]  15.96 39.88 0 bottom
PR471  10_6  [R0603]  31.15 109.05 0 bottom
PR472  2.2_8  [R0805]  36.59 100.31 270 top
PR474  52.3K/F_4  [R0402]  37 110.85 270 bottom
PR475  1_6  [R0603]  31.43 105.85 0 bottom
PR477  100K/F_4  [R0402]  38.01 110.85 270 bottom
PR478  16.5K/F_4  [R0402]  36.04 110.85 90 bottom
PR479  10K_4  [R0402]  20.77 46.97 90 bottom
PR480  *0_4_NC  [R0402]  21.88 46.97 90 bottom
PR481  *0_4_NC  [R0402]  16.41 51.34 180 bottom
PR483  1_6  [R0603]  74.81 10.86 180 bottom
PR484  100K_4  [R0402]  131.89 31.22 0 bottom
PR485  100K_4  [R0402]  134.35 27.46 270 bottom
PR492  *0_4_NC  [R0402]  39.49 110.99 0 top
PR493  *100_4_NC  [R0402]  30.19 97.21 90 bottom
PR494  *SJ0402_NC  [S0402]  30.19 95.18 90 bottom
PR495  *SJ0402_NC  [S0402]  39.49 110.03 0 top
PR496  *SJ0402_NC  [S0402]  147.23 51.48 180 bottom
PR498  *10K_4_NC  [R0402]  19.74 49.76 180 bottom
PR499  *0_4_NC  [R0402]  170.04 22.98 180 bottom
PR500  *0_4_NC  [R0402]  127.29 22.59 180 bottom
PR501  10K_4  [R0402]  127.29 23.6 180 bottom
PR502  10K_4  [R0402]  170.04 24.34 180 bottom
PR503  *0_4_NC  [R0402]  30.04 76.69 0 bottom
PR504  10K_4  [R0402]  30.04 77.7 0 bottom
PR505  *0_4_NC  [R0402]  135.7 31.65 180 bottom
PR506  10K_4  [R0402]  135.7 30.56 180 bottom
PR507  *10K_4_NC  [R0402]  106.75 138.07 270 bottom
PR508  *SJ0402_NC  [S0402]  107.77 138.07 90 bottom
PR509  *10K_4_NC  [R0402]  35.06 127.16 90 bottom
PR510  *SJ0402_NC  [S0402]  127.22 48.14 90 bottom
PR511  *SJ0402_NC  [S0402]  144.84 37.42 270 top
PR512  *SJ0402_NC  [S0402]  134.71 53.8 0 bottom
PR513  10K_4  [R0402]  147.62 36.7 0 bottom
PR514  10K_4  [R0402]  32.81 108.55 270 top
PR515  *2.2_12_NC  [R1206]  62.68 6.46 270 top
PU2  RT6575CGQW  [QFN20-3X3-4-26P]  149.67 10.52 0 bottom
PU9  M5388K11U  [QFN32-4X4-4-26P]  21.02 40.24 0 bottom
PU15  BQ24780SRUYR  [QFN28-4X4-4-38P]  69.94 11.84 180 bottom
PU16  ISL62771HRTZ-T  [QFN40-5X5-4-41P-ISL62771-SMT]  113.1 143.66 270 bottom
PU17  ISL62771HRTZ-T  [QFN40-5X5-4-41P-ISL62771-SMT]  39.4 121.89 180 bottom
PU18  G5335QT2U  [QFN23-4X4-5-SMT]  35.75 107.04 0 bottom
PU19  G5335AQT2U  [QFN23-4X4-5-SMT]  142.94 35.31 270 bottom
PU20  G9336ADJTP1U  [SOT23-2_8-95-6P]  125.41 51.57 90 bottom
PU21  G9661MF11U  [SOP8-6-1_27-9P]  120.59 35.41 180 bottom
PU23  G9661MF11U  [SOP8-6-1_27-9P]  21.87 52.94 90 bottom
PU24  ISL62771HRTZ-T  [QFN40-5X5-4-41P-ISL62771-SMT]  140.78 49.76 180 bottom
PU25  G5335QT2U  [QFN23-4X4-5-SMT]  169.36 63.35 180 bottom
PU27  AOZ1331DI  [SON14-3X2-4-15P-SMT]  121.32 24.82 270 bottom
PU28  AOZ1331DI  [SON14-3X2-4-15P-SMT]  164.76 23.7 270 bottom
PU29  AOZ1331DI  [SON14-3X2-4-15P-SMT]  153.73 26.14 0 bottom
PU30  AS393MTR-E1  [SOIC8-6-1_27]  117.7 64.75 180 bottom
Q4  MMST3904-7-F  [UMT_213-3-1_3]  70.07 104.75 270 top
Q6  2N7002W  [UMT_213-3-1_3]  173.05 47.42 90 top
Q7  PJA3409  [SOT23_213-3_3-2]  181.8 46.59 270 top
Q8  2N7002K  [SOT23_213-3_3-2]  185.61 46.59 270 top
Q9  DMN5L06DWK/50V_0.302A  [SC70-2_1-65-6P-1_1H]  170.37 39.73 90 top
Q11  2N7002K  [SOT23_213-3_3-2]  100.52 34.42 270 top
Q12  2N7002W  [UMT_213-3-1_3]  246.95 23.22 180 top
Q13  2N7002KDW  [SOT-363]  198.64 22.41 270 top
Q16  2N7002KDW  [SOT-363]  199.68 18.19 90 top
Q17  2N7002W  [UMT_213-3-1_3]  43.17 107.19 180 top
Q20  LTA014YUBFS8TL  [UMT_213-3-1_3]  28.51 64.37 180 bottom
Q21  2N7002W  [UMT_213-3-1_3]  28.51 60.3 180 bottom
Q23  2N7002KDW  [SOT-363]  261.3 55 90 bottom
Q25  2N7002KDW  [SOT-363]  179.24 36.99 270 bottom
Q26  2N7002K  [SOT23_213-3_3-2]  173.9 36.63 270 bottom
Q30  2N7002W  [UMT_213-3-1_3]  227.57 16.95 180 bottom
Q31  2N7002KDW  [SOT-363]  232.8 16.49 0 bottom
Q32  DMN5L06DWK/50V_0.302A  [SC70-2_1-65-6P-1_1H]  39.94 99.55 0 bottom
Q33  DMN5L06DWK/50V_0.302A  [SC70-2_1-65-6P-1_1H]  41.62 101.33 90 top
Q36  2N7002KDW  [SOT-363]  91.25 123.68 0 bottom
Q37  2N7002K  [SOT23_213-3_3-2]  101.9 107.57 270 top
Q40  2N7002KDW  [SOT-363]  127.45 84.56 0 bottom
Q41  2N7002KDW  [SOT-363]  220.08 16.74 270 bottom
Q42  2N7002K  [SOT23_213-3_3-2]  212.28 17.89 90 top
Q44  DMN5L06DWK/50V_0.302A  [SC70-2_1-65-6P-1_1H]  44.39 101.33 90 top
Q45  2N7002W  [UMT_213-3-1_3]  133.8 82.63 270 top
Q49  2N7002W  [UMT_213-3-1_3]  269.3 79.86 270 top
Q50  *2N7002W_NC  [UMT_213-3-1_3]  119.67 84.89 0 bottom
Q51  2N7002W  [UMT_213-3-1_3]  151.19 51.03 90 bottom
Q52  *2N7002W_NC  [UMT_213-3-1_3]  136.56 26.42 0 bottom
Q53  *2N7002W_NC  [UMT_213-3-1_3]  102.1 123.03 180 bottom
Q54  *2N7002W_NC  [UMT_213-3-1_3]  80.54 126.37 270 bottom
Q55  *2N7002W_NC  [UMT_213-3-1_3]  60.03 126.32 270 bottom
Q56  *2N7002W_NC  [UMT_213-3-1_3]  115.08 22.5 180 bottom
Q57  *2N7002W_NC  [UMT_213-3-1_3]  14.9 9.81 0 bottom
Q58  *2N7002W_NC  [UMT_213-3-1_3]  136.44 23.48 180 bottom
Q59  *2N7002W_NC  [UMT_213-3-1_3]  28.44 67.39 0 bottom
Q60  *2N7002W_NC  [UMT_213-3-1_3]  129.39 43.39 270 bottom
Q61  *2N7002W_NC  [UMT_213-3-1_3]  126.45 43.39 270 bottom
Q62  *2N7002W_NC  [UMT_213-3-1_3]  126.33 81.05 180 bottom
Q63  *2N7002W_NC  [UMT_213-3-1_3]  129.74 81.05 0 bottom
Q64  *2N7002W_NC  [UMT_213-3-1_3]  115.33 112.76 270 top
R43  75_4  [R0402]  276.03 105.37 180 top
R45  75_4  [R0402]  276.03 104.1 180 top
R53  75_4  [R0402]  275.65 97.75 180 top
R54  75_4  [R0402]  275.65 96.48 180 top
R55  10K_4  [R0402]  33.29 93.4 270 top
R58  2.49K/F_4  [R0402]  277.2 90.53 180 top
R73  1K/F_4  [R0402]  270.45 83.16 90 top
R75  10K_4  [R0402]  170.33 79.09 0 top
R83  2.2K_4  [R0402]  276.41 68.76 180 top
R84  2.2K_4  [R0402]  277.81 70.11 270 top
R92  *4.7K_4_NC  [R0402]  266.46 69.58 0 top
R93  3.9K/F_4  [R0402]  276.41 67.53 0 top
R94  *4.7K_4_NC  [R0402]  266.46 67.95 0 top
R95  *4.7K_4_NC  [R0402]  276.41 66.57 180 top
R96  *4.7K_4_NC  [R0402]  276.92 65.61 180 top
R97  *4.7K_4_NC  [R0402]  276.92 64.65 180 top
R110  10K_4  [R0402]  179.44 45.93 90 top
R112  10K_4  [R0402]  173.72 50.58 90 top
R117  10K_4  [R0402]  179.9 48.11 180 top
R118  120/F_6  [R0603]  184.98 49.26 180 top
R122  100K_4  [R0402]  175.11 46.86 90 top
R128  78.7K/F_4  [R0402]  262.87 45.06 180 top
R132  100K_4  [R0402]  272.2 42.93 90 top
R133  22.6K/F_4  [R0402]  262.87 44.05 180 top
R135  100K_4  [R0402]  179.64 42.52 0 top
R138  *s0402_NC  [S0402]  184.98 42.02 180 top
R150  4.7K_4  [R0402]  164.05 39.38 270 top
R151  4.7K_4  [R0402]  165.19 39.38 270 top
R159  *0_4_NC  [R0402]  168.47 37.7 270 top
R161  *s0402_NC  [S0402]  164.05 37.5 270 top
R162  *s0402_NC  [S0402]  165.19 37.5 270 top
R163  *0_4_NC  [R0402]  170.88 37.32 180 top
R170  10K_4  [R0402]  166.26 35.67 90 top
R171  10K_4  [R0402]  167.27 35.67 90 top
R172  1K/F_4  [R0402]  168.47 35.67 270 top
R173  1K/F_4  [R0402]  170.12 35.67 270 top
R178  200K_4  [R0402]  103.31 34.8 270 top
R179  100K_4  [R0402]  104.45 34.8 270 top
R201  10K_4  [R0402]  233.74 31.67 90 top
R202  *s0402_NC  [S0402]  231.36 32.06 0 top
R226  *s0402_NC  [S0402]  220.08 13.85 90 bottom
R228  *s0402_NC  [S0402]  230.94 12.91 0 bottom
R231  *0_4_NC  [R0402]  107.63 25.51 90 top
R232  *0_4_NC  [R0402]  104.59 25.51 270 top
R233  *0_4_NC  [R0402]  103.57 25.51 270 top
R234  *s0402_NC  [S0402]  28.01 17.12 0 top
R235  10K_4  [R0402]  8.6 16.18 0 top
R236  *0_4_NC  [R0402]  106.62 25.51 270 top
R238  *0_4_NC  [R0402]  199.2 15.09 270 top
R239  10K_4  [R0402]  200.32 15.09 90 top
R241  10K_4  [R0402]  8.6 15.09 0 top
R242  *0_4_NC  [R0402]  105.6 25.51 270 top
R246  *s0402_NC  [S0402]  26.86 10.65 0 top
R248  *s0402_NC  [S0402]  26.86 9.63 0 top
R262  18.7K/F_4  [R0402]  45.76 109.12 90 bottom
R263  100K_4  [R0402]  44.59 109.61 90 top
R264  2K/F_4  [R0402]  42.86 109.2 180 top
R303  1K/F_4  [R0402]  272.66 83.57 0 bottom
R320  *s0402_NC  [S0402]  274 79.86 0 top
R321  10K_4  [R0402]  270.24 84.03 180 bottom
R324  120/F_4  [R0402]  275.78 79.38 270 top
R325  *s0402_NC  [S0402]  274 78.85 0 top
R329  *s0402_NC  [S0402]  274 77.7 0 top
R330  120/F_4  [R0402]  275.78 77.22 270 top
R333  *s0402_NC  [S0402]  274 76.69 0 top
R336  *s0402_NC  [S0402]  275.65 73.39 0 top
R337  120/F_4  [R0402]  277.43 72.93 270 top
R340  *s0402_NC  [S0402]  275.65 72.37 0 top
R341  *s0402_NC  [S0402]  275.65 75.67 0 top
R342  120/F_4  [R0402]  277.43 75.19 270 top
R344  *s0402_NC  [S0402]  275.65 74.66 0 top
R345  *4.7K_4_NC  [R0402]  271.15 69.09 0 bottom
R346  *4.7K_4_NC  [R0402]  276.41 66.55 180 bottom
R347  *4.7K_4_NC  [R0402]  276.41 65.54 180 bottom
R348  *4.7K_4_NC  [R0402]  274.03 65.82 0 bottom
R349  4.7K_4  [R0402]  276.41 64.49 180 bottom
R350  150_4  [R0402]  29.51 62.38 180 bottom
R352  10K_4  [R0402]  26.24 60.03 270 bottom
R358  *s0402_NC  [S0402]  166.82 54.08 90 bottom
R359  *s0402_NC  [S0402]  167.96 54.08 90 bottom
R376  *s0402_NC  [S0402]  175.96 54.72 90 bottom
R377  *s0402_NC  [S0402]  176.98 54.72 90 bottom
R378  *s0402_NC  [S0402]  178.12 54.72 90 bottom
R379  *s0402_NC  [S0402]  179.13 54.72 90 bottom
R393  100K_4  [R0402]  265.09 53.98 270 bottom
R394  10K_4  [R0402]  263.97 55.99 270 bottom
R397  1.5K/F_4  [R0402]  239.03 12.1 180 top
R398  100K_4  [R0402]  172.53 54.08 270 bottom
R399  100K_4  [R0402]  260.67 51.59 270 bottom
R404  *s0402_NC  [S0402]  266.77 41.3 0 top
R415  *0_6_NC  [R0603]  170.88 36.53 270 bottom
R416  33_6  [R0603]  181.17 36.56 90 bottom
R417  100K_4  [R0402]  176.31 36.35 90 bottom
R433  *s0402_NC  [S0402]  232.74 29.89 270 top
R435  *10K_4_NC  [R0402]  223.63 17.45 270 bottom
R436  10K_4  [R0402]  230.82 20.71 180 bottom
R443  100K_4  [R0402]  230.32 16.24 90 bottom
R445  100K_4  [R0402]  223.89 14.08 90 bottom
R446  1.5K/F_4  [R0402]  239 14.43 180 top
R447  *10K_4_NC  [R0402]  230.32 14.33 90 bottom
R448  100K_4  [R0402]  231.33 14.33 270 bottom
R452  *s0402_NC  [S0402]  12.38 7.73 180 bottom
R453  *s0402_NC  [S0402]  12.38 8.74 180 bottom
R459  *SHORT_6_NC  [S0603]  194.88 17.25 180 bottom
R460  *0_4_NC  [R0402]  167.32 41.25 0 top
R461  196/F_4  [R0402]  68.61 112.3 270 top
R462  196/F_4  [R0402]  70.09 113.18 90 top
R463  39.2/F_4  [R0402]  73.42 92.52 270 top
R464  39.2/F_4  [R0402]  76.8 85.65 0 bottom
R467  300_4  [R0402]  55.44 105.39 180 top
R468  300_4  [R0402]  46.29 101.28 180 bottom
R469  2.2K_4  [R0402]  39.62 102.09 90 bottom
R470  2.2K_4  [R0402]  40.58 102.09 90 bottom
R471  1K/F_4  [R0402]  50.86 107.78 180 bottom
R472  150/F_4  [R0402]  48.58 114.79 180 bottom
R473  1K/F_4  [R0402]  50.86 104.73 180 bottom
R474  1K/F_4  [R0402]  48.58 103.45 0 bottom
R475  1K/F_4  [R0402]  46.27 103.65 180 bottom
R476  2K/F_4  [R0402]  50.86 114.79 0 bottom
R477  *1K/F_4_NC  [R0402]  46.29 105.75 0 bottom
R478  *2.2K_4_NC  [R0402]  46.29 100.3 0 bottom
R479  *1K/F_4_NC  [R0402]  43.86 96.48 270 top
R480  *1K/F_4_NC  [R0402]  50.86 109 0 bottom
R481  2.2K_4  [R0402]  43.7 104.14 0 top
R482  2.2K_4  [R0402]  44.06 98.68 180 top
R483  *1K/F_4_NC  [R0402]  50.86 113.77 0 bottom
R484  *s0402_NC  [S0402]  50.86 105.75 0 bottom
R485  *1K/F_4_NC  [R0402]  48.58 113.77 180 bottom
R486  *s0402_NC  [S0402]  45.89 96.48 90 top
R487  *1K/F_4_NC  [R0402]  50.86 112.76 0 bottom
R488  *1K/F_4_NC  [R0402]  48.58 112.76 180 bottom
R489  1K/F_4  [R0402]  48.58 110.01 180 bottom
R490  1K/F_4  [R0402]  50.86 110.01 0 bottom
R491  *220_4_NC  [R0402]  48.58 101.44 0 bottom
R492  *220_4_NC  [R0402]  44.87 96.48 270 top
R493  *220_4_NC  [R0402]  48.58 105.75 180 bottom
R494  *s0402_NC  [S0402]  50.86 106.76 0 bottom
R495  *s0402_NC  [S0402]  50.86 103.45 0 bottom
R496  1K/F_4  [R0402]  48.58 111.61 0 bottom
R497  *1K/F_4_NC  [R0402]  50.86 111.61 0 bottom
R498  *1K/F_4_NC  [R0402]  46.29 104.73 0 bottom
R499  *1K/F_4_NC  [R0402]  48.58 104.73 0 bottom
R500  *1K/F_4_NC  [R0402]  48.58 109 180 bottom
R501  *1K/F_4_NC  [R0402]  46.29 106.76 0 bottom
R502  *1K/F_4_NC  [R0402]  46.29 102.3 0 bottom
R503  *s0402_NC  [S0402]  46.32 114.86 180 bottom
R505  *s0402_NC  [S0402]  46.32 113.72 180 bottom
R506  *220_4_NC  [R0402]  48.58 106.76 180 bottom
R507  *220_4_NC  [R0402]  48.58 102.46 0 bottom
R508  1K/F_4  [R0402]  38.42 26.52 270 top
R509  1K/F_4  [R0402]  49.47 28.68 180 top
R510  1K/F_4  [R0402]  49.47 27.41 180 top
R511  *s0402_NC  [S0402]  49.47 26.14 0 top
R512  1K/F_4  [R0402]  51.5 25 180 top
R513  33_4  [R0402]  38.8 23.86 0 top
R514  1K/F_4  [R0402]  49.47 25 0 top
R515  10K/F_4  [R0402]  38.82 22.43 180 top
R516  1K/F_4  [R0402]  49.47 23.73 0 top
R517  10K/F_4  [R0402]  38.8 21.14 180 top
R518  10K/F_4  [R0402]  38.8 19.94 180 top
R519  33_4  [R0402]  49.47 19.61 0 top
R520  1K/F_4  [R0402]  49.47 21.75 180 top
R521  33_4  [R0402]  95.95 109.68 180 bottom
R522  33_4  [R0402]  101.54 104.5 180 top
R523  15K/F_4  [R0402]  99.68 111 180 top
R524  2.2K_4  [R0402]  95.95 104.88 0 bottom
R525  2.2K_4  [R0402]  95.95 103.87 0 bottom
R526  *10K/F_4_NC  [R0402]  100.27 105.97 180 bottom
R527  *10K/F_4_NC  [R0402]  100.79 104.62 90 bottom
R528  10K/F_4  [R0402]  95.95 102.11 180 bottom
R530  10K_4  [R0402]  73.2 114.95 0 top
R531  *0_4_NC  [R0402]  80.51 123.71 270 bottom
R532  2.2K_4  [R0402]  73.77 116.48 90 top
R533  2.2K_4  [R0402]  74.94 116.48 90 top
R534  1K/F_4  [R0402]  86.6 113.77 180 top
R535  *10K/F_4_NC  [R0402]  84.49 111.33 90 top
R536  10K/F_4  [R0402]  76.27 120.93 270 bottom
R537  10K/F_4  [R0402]  82.72 111.61 180 top
R538  10K/F_4  [R0402]  83.02 113.79 180 top
R539  10K/F_4  [R0402]  79.71 120.93 270 bottom
R540  1K/F_4  [R0402]  88.85 112.2 90 top
R541  *0_4_NC  [R0402]  88.18 104.71 0 top
R542  1K/F_4  [R0402]  89.91 112.2 90 top
R543  10K/F_4  [R0402]  70.99 116.37 270 top
R544  1K/F_4  [R0402]  84.9 115.42 0 top
R545  10K/F_4  [R0402]  85.15 122.66 90 bottom
R546  10K/F_4  [R0402]  83.76 122.66 90 bottom
R547  10K/F_4  [R0402]  95.95 115.17 180 bottom
R548  10K/F_4  [R0402]  95.95 116.18 180 bottom
R549  10K/F_4  [R0402]  78.7 120.93 270 bottom
R550  10K/F_4  [R0402]  81.85 120.93 270 bottom
R551  *10K/F_4_NC  [R0402]  70.49 115.03 180 top
R552  *10K/F_4_NC  [R0402]  78.09 125.11 180 bottom
R553  20M_4  [R0402]  101.74 116.89 0 top
R554  2.2K_4  [R0402]  97.98 111.07 180 bottom
R555  2.2K_4  [R0402]  97.98 112.09 180 bottom
R556  *2.2K_4_NC  [R0402]  97.98 116.18 180 bottom
R557  *2.2K_4_NC  [R0402]  97.98 117.2 180 bottom
R558  33_4  [R0402]  84.9 116.44 0 top
R559  33_4  [R0402]  89.87 114.23 90 top
R560  2.2K_4  [R0402]  88.33 125.86 0 bottom
R561  33_4  [R0402]  86.3 115.42 90 top
R562  *s0402_NC  [S0402]  88.33 126.88 180 bottom
R563  33_4  [R0402]  88.91 114.2 90 top
R568  *2.2K_4_NC  [R0402]  75.88 117.96 0 top
R569  15K/F_4  [R0402]  76.26 116.57 270 top
R570  100K/F_4  [R0402]  94.04 121.9 180 bottom
R571  *1K/F_4_NC  [R0402]  77.66 115.93 270 top
R572  15K/F_4  [R0402]  78.17 114.41 180 top
R573  *2.2K_4_NC  [R0402]  78.09 124.09 0 bottom
R574  15K/F_4  [R0402]  77.23 120.93 90 bottom
R576  1K/F_4  [R0402]  90.23 120.88 270 bottom
R578  10K/F_4  [R0402]  87.89 112.2 90 top
R579  11.8K/F_4  [R0402]  82.72 112.57 0 top
R580  *10K/F_4_NC  [R0402]  89.95 106.05 90 top
R581  1K/F_4  [R0402]  88.84 122.53 270 bottom
R582  10K/F_4  [R0402]  88.03 106.05 90 top
R583  10K/F_4  [R0402]  88.86 107.52 180 top
R584  *s0402_NC  [S0402]  70.84 124.18 270 bottom
R585  *s0402_NC  [S0402]  71.85 124.18 270 bottom
R586  1M_4  [R0402]  68.39 120.5 180 bottom
R587  1K/F_4  [R0402]  73.39 120.93 90 bottom
R588  *1K/F_4_NC  [R0402]  74.35 120.93 90 bottom
R589  22_4  [R0402]  100.78 107.27 0 bottom
R590  *22_4_NC  [R0402]  100.27 108.67 0 bottom
R591  10K/F_4  [R0402]  74.7 110.57 90 top
R592  *10K/F_4_NC  [R0402]  97.98 107.27 0 bottom
R593  10K/F_4  [R0402]  97.98 108.67 0 bottom
R594  10K/F_4  [R0402]  97.98 105.97 0 bottom
R595  10K/F_4  [R0402]  80.71 115.93 90 top
R596  10K/F_4  [R0402]  72.43 116.32 180 top
R597  10K/F_4  [R0402]  81.73 115.93 90 top
R598  10K/F_4  [R0402]  81.53 123.71 270 bottom
R599  10K/F_4  [R0402]  138.37 149.2 180 top
R600  10K/F_4  [R0402]  138.37 144.89 0 top
R601  10K/F_4  [R0402]  123.89 145.52 180 top
R602  2K/F_4  [R0402]  95.95 107.27 0 bottom
R603  *2K/F_4_NC  [R0402]  95.95 108.67 0 bottom
R604  *2K/F_4_NC  [R0402]  95.95 106.25 0 bottom
R605  *2K/F_4_NC  [R0402]  80.1 113.72 180 top
R606  *2K/F_4_NC  [R0402]  76.11 112.57 270 top
R607  *2K/F_4_NC  [R0402]  83.12 115.42 0 top
R608  *2K/F_4_NC  [R0402]  79.5 123.71 270 bottom
R609  33_4  [R0402]  138.37 146.03 0 top
R610  33_4  [R0402]  123.89 147.55 180 top
R611  33_4  [R0402]  123.89 150.6 180 top
R612  33_4  [R0402]  138.37 147.05 0 top
R613  *s0402_NC  [S0402]  138.37 148.06 180 top
R614  *s0402_NC  [S0402]  123.89 146.54 0 top
R615  *s0402_NC  [S0402]  102.3 100.69 270 top
R616  *s0402_NC  [S0402]  104.33 100.69 270 top
R617  *s0402_NC  [S0402]  103.32 100.69 270 top
R618  *s0402_NC  [S0402]  89.51 102.11 0 top
R619  *s0402_NC  [S0402]  88.84 108.48 0 top
R621  1K/F_4  [R0402]  106.4 108.43 90 top
R622  100K/F_4  [R0402]  104.4 108.43 270 top
R623  *s0402_NC  [S0402]  89.06 98.46 0 top
R624  *s0402_NC  [S0402]  86.42 104.71 0 top
R625  *s0603_NC  [S0603]  82.86 108.74 0 top
R627  1K/F_4  [R0402]  67.27 46.55 90 top
R628  *s0402_NC  [S0402]  80.56 53.6 180 top
R629  1K/F_4  [R0402]  72.04 47.42 90 top
R630  1K/F_4  [R0402]  81.58 47.56 0 top
R632  1K/F_4  [R0402]  86.17 44.73 270 top
R634  1K/F_4  [R0402]  68.1 60.53 270 top
R635  *s0402_NC  [S0402]  81.41 60.44 180 top
R636  1K/F_4  [R0402]  73.85 56.17 0 top
R638  1K/F_4  [R0402]  81.49 56.48 0 top
R640  1K/F_4  [R0402]  85.35 54.99 270 top
R641  10K_4  [R0402]  117.82 108.44 0 top
R642  10K_4  [R0402]  117.82 107.42 0 top
R643  33_4  [R0402]  119.95 108.44 0 top
R644  33_4  [R0402]  119.95 109.58 0 top
R645  *5.1K/F_4_NC  [R0402]  121.1 100.82 0 bottom
R646  *s0402_NC  [S0402]  159.55 123.02 270 bottom
R647  10K/F_4  [R0402]  123.13 99.62 180 bottom
R648  *s0402_NC  [S0402]  124.91 88.24 0 bottom
R649  1K/F_4  [R0402]  123.13 100.82 0 bottom
R650  *10K/F_4_NC  [R0402]  121.1 99.62 180 bottom
R651  *1K/F_4_NC  [R0402]  122.11 102.72 180 bottom
R652  200/F_4  [R0402]  124.91 90.53 0 bottom
R657  *s0402_NC  [S0402]  116.78 87.1 0 bottom
R658  *0_4_NC  [R0402]  123 88.24 0 bottom
R664  40.2/F_4  [R0402]  139.81 131.81 90 top
R665  40.2/F_4  [R0402]  164 123.02 90 bottom
R666  120/F_4  [R0402]  140.86 129.95 90 top
R667  120/F_4  [R0402]  160.69 123.02 90 bottom
R668  49.9/F_4  [R0402]  122.11 112.76 0 bottom
R669  10/F_4  [R0402]  124.14 112.76 180 bottom
R670  100/F_4  [R0402]  139.84 129.95 90 top
R671  49.9/F_4  [R0402]  150.11 84.74 270 bottom
R672  10/F_4  [R0402]  148.08 84.74 270 bottom
R673  100/F_4  [R0402]  162.98 123.02 270 bottom
R674  5.1K/F_4  [R0402]  124.14 111.74 0 bottom
R675  5.1K/F_4  [R0402]  147.04 84.74 90 bottom
R679  10K/F_4  [R0402]  136.36 83.02 180 top
R681  1K/F_4  [R0402]  124.14 106.15 180 bottom
R683  *1K/F_4_NC  [R0402]  122.11 106.15 0 bottom
R688  4.7K_4  [R0402]  119.95 106.15 0 top
R690  4.7K_4  [R0402]  119.95 105.01 0 top
R691  *s0402_NC  [S0402]  128.67 86.85 270 bottom
R693  *s0402_NC  [S0402]  126.75 86.85 270 bottom
R697  *s0402_NC  [S0402]  139.33 83.65 270 top
R698  *s0402_NC  [S0402]  144.23 83.65 270 top
R699  *s0402_NC  [S0402]  138.37 83.65 270 top
R705  1K/F_4  [R0402]  145.99 86.85 90 bottom
R707  10K/F_4  [R0402]  123.39 85.7 270 bottom
R709  1K/F_4  [R0402]  144.07 86.85 90 bottom
R711  *10K/F_4_NC  [R0402]  124.91 89.39 0 bottom
R717  10K_4  [R0402]  117.82 104.93 0 top
R719  10K_4  [R0402]  119.95 103.87 180 top
R720  10K_4  [R0402]  124.14 102.72 180 bottom
R731  4.7K_4  [R0402]  125.79 86.85 90 bottom
R732  4.7K_4  [R0402]  127.71 86.85 90 bottom
R747  10K_4  [R0402]  140.29 83.65 270 top
R748  *10K_4_NC  [R0402]  143.27 83.65 270 top
R749  *10K_4_NC  [R0402]  141.35 83.65 90 top
R750  10K_4  [R0402]  142.31 83.65 90 top
R762  1M_4  [R0402]  116.02 82.4 270 bottom
R763  *s0402_NC  [S0402]  118.81 80.88 180 bottom
R764  *s0402_NC  [S0402]  123.25 82.38 0 bottom
R765  5.1K/F_4  [R0402]  121.86 82.02 90 bottom
R766  *5.1K/F_4  [R0402]  120.87 82.02 270 bottom
R767  16.2K_4  [R0402]  130.26 85.46 270 bottom
R768  60.4/F_4  [R0402]  131.73 134.76 0 top
R769  60.4/F_4  [R0402]  150.45 135.41 180 top
R770  60.4/F_4  [R0402]  173.29 112.16 270 top
R771  60.4/F_4  [R0402]  175.82 92.75 0 top
R772  60.4/F_4  [R0402]  131.73 135.77 0 top
R773  60.4/F_4  [R0402]  150.45 136.43 180 top
R774  60.4/F_4  [R0402]  174.3 112.16 270 top
R775  60.4/F_4  [R0402]  175.82 91.74 0 top
R776  120/F_4  [R0402]  123.38 134.98 90 bottom
R777  120/F_4  [R0402]  158.23 134.22 90 top
R778  120/F_4  [R0402]  175.19 119.01 270 top
R779  120/F_4  [R0402]  173.04 83.16 270 bottom
R780  1K/F_4  [R0402]  131.73 133.74 180 top
R781  1K/F_4  [R0402]  150.45 133.89 0 top
R782  1K/F_4  [R0402]  172.02 112.16 90 top
R783  1K/F_4  [R0402]  173.91 93.26 270 top
R784  1K/F_4  [R0402]  140.48 133.58 270 bottom
